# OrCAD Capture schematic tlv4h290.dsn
size A
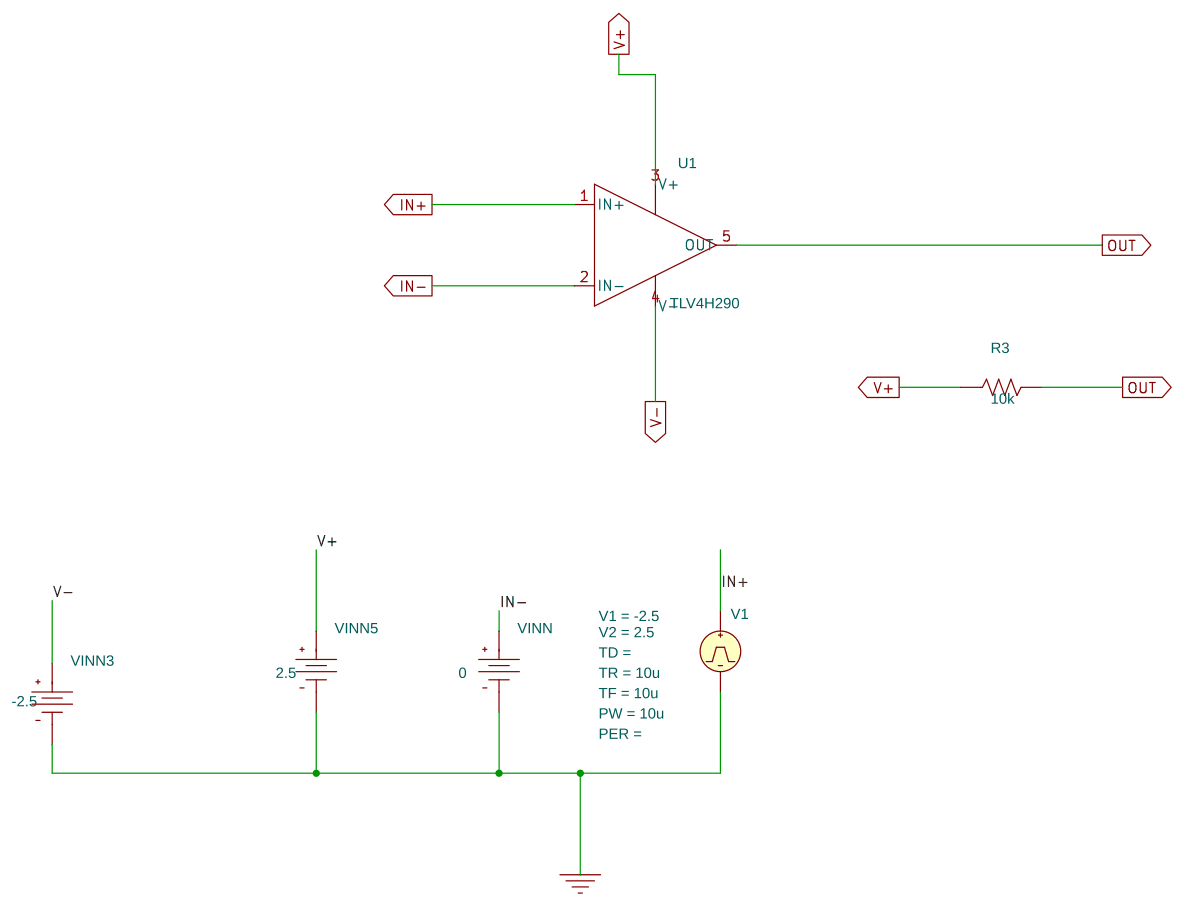
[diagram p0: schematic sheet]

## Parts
R3  10k  [AXRC05]
U1  TLV4H290
V1  VPULSE
VINN  VDC
VINN3  VDC
VINN5  VDC

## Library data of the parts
R3 = R
U1 = TLV4H290
V1 = VPULSE: PW: 10u; TF: 10u; TR: 10u; V1: -2.5; V2: 2.5
VINN = VDC: DC: 0
VINN3 = VDC: DC: -2.5
VINN5 = VDC: DC: 2.5

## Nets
0: V1.2(-) VINN.1(-) VINN3.1(-) VINN5.1(-)
IN+: U1.1(IN+) V1.1(+)
IN-: U1.2(IN-) VINN.0(+)
OUT: R3.2 U1.5(OUT)
V+: R3.1 U1.3(V+) VINN5.0(+)
V-: U1.4(V-) VINN3.0(+)
